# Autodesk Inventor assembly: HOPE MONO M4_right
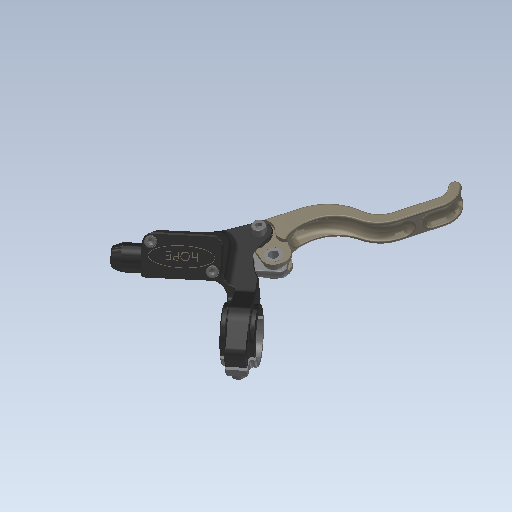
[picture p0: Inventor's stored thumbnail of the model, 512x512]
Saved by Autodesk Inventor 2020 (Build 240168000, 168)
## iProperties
Created: 2017-10
Part Number: HOPE MONO M4_right
Material: Ogólny
Document SubType Name: Assembly
Designer: Tomasz
Sending System: SolidWorks 2017
Last Author: Tomasz
Last Saved: 2017-11-19
Author: Tomasz
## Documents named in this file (11)
- C:\Users\bruno\Documents\1-Cours-2020-21\1STI2D-2020-21\IT\6. Antivol\Inventor-Antivol\INVENTOR 2018_Steel Hardtail B+\HOPE MONO M4_right.iam
- C:\Users\bruno\Documents\1-Cours-2020-21\1STI2D-2020-21\IT\6. Antivol\Inventor-Antivol\INVENTOR 2018_Steel Hardtail B+\HOPE MONO M4 klamka.ipt
- C:\Users\bruno\Documents\1-Cours-2020-21\1STI2D-2020-21\IT\6. Antivol\Inventor-Antivol\INVENTOR 2018_Steel Hardtail B+\HOPE MONO M4 korpus klamki.ipt
- C:\Users\bruno\Documents\1-Cours-2020-21\1STI2D-2020-21\IT\6. Antivol\Inventor-Antivol\INVENTOR 2018_Steel Hardtail B+\HOPE MONO M4 obejma klamki.ipt
- C:\Users\bruno\Documents\1-Cours-2020-21\1STI2D-2020-21\IT\6. Antivol\Inventor-Antivol\INVENTOR 2018_Steel Hardtail B+\HOPE MONO M4 pokrywa zbiornika korpusu klamki.ipt
- C:\Users\bruno\Documents\1-Cours-2020-21\1STI2D-2020-21\IT\6. Antivol\Inventor-Antivol\INVENTOR 2018_Steel Hardtail B+\t_X2_0142_X0_oczek.ipt
- C:\Users\bruno\Documents\1-Cours-2020-21\1STI2D-2020-21\IT\6. Antivol\Inventor-Antivol\INVENTOR 2018_Steel Hardtail B+\M4 x 6.ipt
- C:\Users\bruno\Documents\1-Cours-2020-21\1STI2D-2020-21\IT\6. Antivol\Inventor-Antivol\INVENTOR 2018_Steel Hardtail B+\ISO 4762 - M4 x 10ISO.ipt
- C:\Users\bruno\Documents\1-Cours-2020-21\1STI2D-2020-21\IT\6. Antivol\Inventor-Antivol\INVENTOR 2018_Steel Hardtail B+\ISO 4762 - M4 x 16ISO.ipt
- C:\Users\bruno\Documents\1-Cours-2020-21\1STI2D-2020-21\IT\6. Antivol\Inventor-Antivol\INVENTOR 2018_Steel Hardtail B+\nakr_X2_0119_X0_tka.ipt
- C:\Users\bruno\Documents\1-Cours-2020-21\1STI2D-2020-21\IT\6. Antivol\Inventor-Antivol\INVENTOR 2018_Steel Hardtail B+\_X2_01420105_X0_cznik klamki.ipt
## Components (12 placed, 10 different names)
1. HOPE MONO M4 klamka:1
2. HOPE MONO M4 korpus klamki:1
3. HOPE MONO M4 obejma klamki:1
4. HOPE MONO M4 pokrywa zbiornika korpusu klamki:1
5. t_X2_0142_X0_oczek:1
6. M4 x 6:1
7. M4 x 6:2
8. ISO 4762 - M4 x 10ISO:1
9. ISO 4762 - M4 x 10ISO:2
10. ISO 4762 - M4 x 16ISO:1
11. nakr_X2_0119_X0_tka:1
12. _X2_01420105_X0_cznik klamki:1
